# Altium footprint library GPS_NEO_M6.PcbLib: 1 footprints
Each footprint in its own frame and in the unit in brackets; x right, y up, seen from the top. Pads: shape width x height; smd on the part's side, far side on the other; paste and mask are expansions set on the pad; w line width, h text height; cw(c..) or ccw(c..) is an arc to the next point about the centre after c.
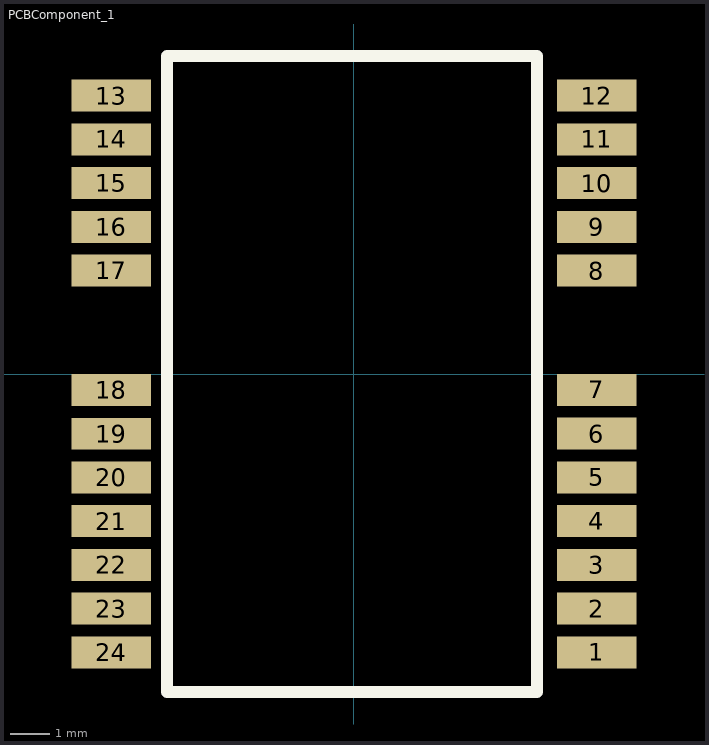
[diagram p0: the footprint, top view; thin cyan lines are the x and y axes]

## PCBComponent_1 [mm]
pads (25):
  rect 2x0.8 smd: 1(6.1,-7) 2(6.1,-5.9) 3(6.1,-4.8) 4(6.1,-3.7) 5(6.1,-2.6) 6(6.1,-1.5) 7(6.1,-0.4) 8(6.1,2.6) 9(6.1,3.7) 10(6.1,4.8) 11(6.1,5.9) 12(6.1,7) 13(-6.1,7) 14(-6.1,5.9) 15(-6.1,4.8) 16(-6.1,3.7) 17(-6.1,2.6) 18(-6.1,-0.4) 19(-6.1,-1.5) 20(-6.1,-2.6) 21(-6.1,-3.7) 22(-6.1,-4.8) 23(-6.1,-5.9) 24(-6.1,-7)
  round 1 on Top Overlay: ""(3.5,-7)
Top Overlay:
  lines w0.3: -4.7,-8 -4.7,8 4.6,8 4.6,-8 -4.7,-8
3D body: height 2.64, standoff 0, extent -5.98,-8.3 6.38,8.3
